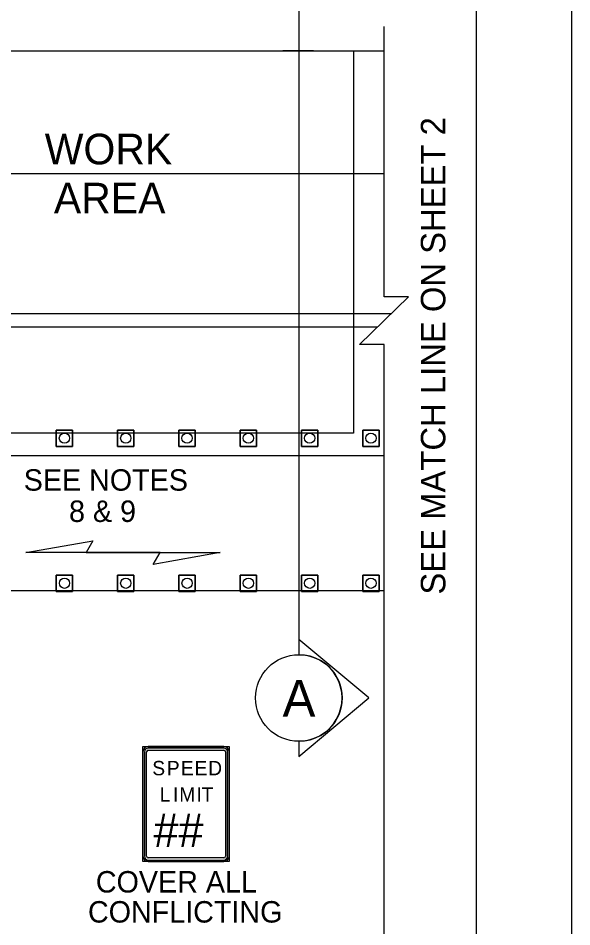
# Model space of a CAD drawing. Extents: x 99979.8 to 100075.7, y 99995 to 100010.7.
# Drawn here: x 100014.256 to 100016.062, y 100005.082 to 100008.046 of the extents above; entities that cross this region are included whole.
import ezdxf

# ---------------------------------------------------------------- set-up
doc = ezdxf.new("R2010")
doc.units = 0
for name, color, linetype in [('RD_ED_ShoulderPavedEdge', 7, 'Continuous'), ('RD_MK_LineEdgeWhite', 7, 'Continuous'), ('RD_MK_LineNoPass', 7, 'Continuous'), ('SH_GI_PlotLimits', 7, 'Continuous'), ('SH_GI_SheetBorder', 7, 'Continuous'), ('SH_TI_WZSectionCut', 7, 'Continuous'), ('TR_SN_ConstructionSigns', 7, 'Continuous'), ('TR_WZ_TrafficCone', 7, 'Continuous'), ('TR_WZ_WorkAreaLabel', 7, 'Continuous'), ('TR_WZ_WorkZoneDetails', 7, 'Continuous'), ('TR_WZ_WorkZoneTextCurrent', 7, 'Continuous')]:
    doc.layers.add(name, color=color, linetype=linetype)

msp = doc.modelspace()

# ---------------------------------------------------------------- linework, layer by layer
at = {"layer": 'RD_ED_ShoulderPavedEdge'}
for p, q in [((100000.1076, 100007.9393), (100015.45, 100007.9393)), ((100015.2197, 100007.9393), (100015.1196, 100007.9393)), ((100000.1076, 100006.1793), (100015.45, 100006.1793))]:
    msp.add_line(p, q, dxfattribs=at)
at = {"layer": 'RD_MK_LineEdgeWhite'}
for p, q in [((100013.0613, 100007.5393), (100015.45, 100007.5393)), ((100013.0469, 100006.6193), (100015.45, 100006.6193))]:
    msp.add_line(p, q, dxfattribs=at)
at = {"layer": 'RD_MK_LineNoPass'}
for p, q in [((100013.0613, 100007.0826), (100015.4741, 100007.0826)), ((100013.0613, 100007.0393), (100015.4293, 100007.0393))]:
    msp.add_line(p, q, dxfattribs=at)
at = {"layer": 'SH_GI_PlotLimits'}
msp.add_lwpolyline([(99999.0625, 99999.6875), (100016.0625, 99999.6875), (100016.0625, 100010.6875), (99999.0625, 100010.6875)], close=True, dxfattribs=at)
at = {"layer": 'SH_GI_SheetBorder'}
msp.add_line((100015.75, 100010.375), (100015.75, 100000), dxfattribs=at)
at = {"layer": 'SH_TI_WZSectionCut'}
for p, q in [((100015.1718, 100008.0993), (100015.1718, 100006.0193)), ((100015.1718, 100006.0193), (100015.1718, 100005.9694)), ((100015.4, 100005.8282), (100015.1718, 100006.0193)), ((100015.1718, 100005.637), (100015.4, 100005.8282)), ((100015.1718, 100005.687), (100015.1718, 100005.637))]:
    msp.add_line(p, q, dxfattribs=at)
msp.add_circle((100015.1718, 100005.8282), 0.1412, dxfattribs=at)
msp.add_arc((100015.1718, 100005.8282), 0.1412, 269.9978, 90.0022, dxfattribs=at)
at = {"layer": 'TR_SN_ConstructionSigns'}
for p, q in [((100014.6809, 100005.6698), (100014.927, 100005.6698)), ((100014.927, 100005.6698), (100014.6809, 100005.6698)), ((100014.6633, 100005.3123), (100014.6633, 100005.6522)), ((100014.6633, 100005.6522), (100014.6633, 100005.3123)), ((100014.6682, 100005.6522), (100014.6682, 100005.3123)), ((100014.6751, 100005.3123), (100014.6751, 100005.6522)), ((100014.927, 100005.6649), (100014.6809, 100005.6649)), ((100014.6809, 100005.658), (100014.927, 100005.658)), ((100014.9329, 100005.6522), (100014.9329, 100005.3123)), ((100014.9397, 100005.3123), (100014.9397, 100005.6522)), ((100014.9446, 100005.6522), (100014.9446, 100005.3123)), ((100014.9446, 100005.3123), (100014.9446, 100005.6522)), ((100014.927, 100005.3065), (100014.6809, 100005.3065)), ((100014.6809, 100005.2996), (100014.927, 100005.2996)), ((100014.927, 100005.2948), (100014.6809, 100005.2948)), ((100014.6809, 100005.2948), (100014.927, 100005.2948))]:
    msp.add_line(p, q, dxfattribs=at)
msp.add_lwpolyline([(100014.6633, 100005.6698), (100014.9446, 100005.6698), (100014.9446, 100005.2948), (100014.6633, 100005.2948)], close=True, dxfattribs=at)
for centre, radius, start, end in [((100014.6809, 100005.6522), 0.0176, 90, 180), ((100014.6809, 100005.6522), 0.0176, 90, 180), ((100014.927, 100005.6522), 0.0176, 0, 90), ((100014.927, 100005.6522), 0.0176, 0, 90), ((100014.6809, 100005.6522), 0.0127, 90, 180), ((100014.6809, 100005.6522), 0.00586, 90, 180), ((100014.927, 100005.6522), 0.0127, 0, 90), ((100014.927, 100005.6522), 0.00586, 360, 90), ((100014.6809, 100005.3123), 0.0176, 180, 270), ((100014.6809, 100005.3123), 0.0176, 180, 270), ((100014.6809, 100005.3123), 0.0127, 180, 270), ((100014.6809, 100005.3123), 0.00586, 180, 270), ((100014.927, 100005.3123), 0.0176, 270, 0), ((100014.927, 100005.3123), 0.0127, 270, 360), ((100014.927, 100005.3123), 0.00586, 270, 0), ((100014.927, 100005.3123), 0.0176, 270, 0)]:
    msp.add_arc(centre, radius, start, end, dxfattribs=at)
at = {"layer": 'TR_WZ_TrafficCone'}
for points in [[(100014.4339, 100006.7026), (100014.3805, 100006.7026), (100014.3805, 100006.6493), (100014.4339, 100006.6493), (100014.4339, 100006.7026)], [(100014.4339, 100006.6493), (100014.3805, 100006.6493), (100014.3805, 100006.7026), (100014.4339, 100006.7026), (100014.4339, 100006.6493)], [(100014.6339, 100006.7026), (100014.5805, 100006.7026), (100014.5805, 100006.6493), (100014.6339, 100006.6493), (100014.6339, 100006.7026)], [(100014.6339, 100006.6493), (100014.5805, 100006.6493), (100014.5805, 100006.7026), (100014.6339, 100006.7026), (100014.6339, 100006.6493)], [(100014.8339, 100006.7026), (100014.7805, 100006.7026), (100014.7805, 100006.6493), (100014.8339, 100006.6493), (100014.8339, 100006.7026)], [(100014.8339, 100006.6493), (100014.7805, 100006.6493), (100014.7805, 100006.7026), (100014.8339, 100006.7026), (100014.8339, 100006.6493)], [(100015.0339, 100006.7026), (100014.9805, 100006.7026), (100014.9805, 100006.6493), (100015.0339, 100006.6493), (100015.0339, 100006.7026)], [(100015.0339, 100006.6493), (100014.9805, 100006.6493), (100014.9805, 100006.7026), (100015.0339, 100006.7026), (100015.0339, 100006.6493)], [(100015.2339, 100006.7026), (100015.1805, 100006.7026), (100015.1805, 100006.6493), (100015.2339, 100006.6493), (100015.2339, 100006.7026)], [(100015.2339, 100006.6493), (100015.1805, 100006.6493), (100015.1805, 100006.7026), (100015.2339, 100006.7026), (100015.2339, 100006.6493)], [(100015.4339, 100006.7026), (100015.3805, 100006.7026), (100015.3805, 100006.6493), (100015.4339, 100006.6493), (100015.4339, 100006.7026)], [(100015.4339, 100006.6493), (100015.3805, 100006.6493), (100015.3805, 100006.7026), (100015.4339, 100006.7026), (100015.4339, 100006.6493)], [(100014.3806, 100006.2293), (100014.434, 100006.2293), (100014.434, 100006.176), (100014.3806, 100006.176), (100014.3806, 100006.2293)], [(100014.3806, 100006.176), (100014.434, 100006.176), (100014.434, 100006.2293), (100014.3806, 100006.2293), (100014.3806, 100006.176)], [(100014.5806, 100006.2293), (100014.634, 100006.2293), (100014.634, 100006.176), (100014.5806, 100006.176), (100014.5806, 100006.2293)], [(100014.5806, 100006.176), (100014.634, 100006.176), (100014.634, 100006.2293), (100014.5806, 100006.2293), (100014.5806, 100006.176)], [(100014.7806, 100006.2293), (100014.834, 100006.2293), (100014.834, 100006.176), (100014.7806, 100006.176), (100014.7806, 100006.2293)], [(100014.7806, 100006.176), (100014.834, 100006.176), (100014.834, 100006.2293), (100014.7806, 100006.2293), (100014.7806, 100006.176)], [(100014.9806, 100006.2293), (100015.034, 100006.2293), (100015.034, 100006.176), (100014.9806, 100006.176), (100014.9806, 100006.2293)], [(100014.9806, 100006.176), (100015.034, 100006.176), (100015.034, 100006.2293), (100014.9806, 100006.2293), (100014.9806, 100006.176)], [(100015.1806, 100006.2293), (100015.234, 100006.2293), (100015.234, 100006.176), (100015.1806, 100006.176), (100015.1806, 100006.2293)], [(100015.1806, 100006.176), (100015.234, 100006.176), (100015.234, 100006.2293), (100015.1806, 100006.2293), (100015.1806, 100006.176)], [(100015.3806, 100006.2293), (100015.434, 100006.2293), (100015.434, 100006.176), (100015.3806, 100006.176), (100015.3806, 100006.2293)], [(100015.3806, 100006.176), (100015.434, 100006.176), (100015.434, 100006.2293), (100015.3806, 100006.2293), (100015.3806, 100006.176)]]:
    msp.add_lwpolyline(points, dxfattribs=at)
for centre in [(100014.4072, 100006.676), (100014.6072, 100006.676), (100014.8072, 100006.676), (100015.0072, 100006.676), (100015.2072, 100006.676), (100015.4072, 100006.676), (100014.4073, 100006.2026), (100014.6073, 100006.2026), (100014.8073, 100006.2026), (100015.0073, 100006.2026), (100015.2073, 100006.2026), (100015.4073, 100006.2026)]:
    msp.add_circle(centre, 0.0167, dxfattribs=at)
at = {"layer": 'TR_WZ_WorkZoneDetails'}
for p, q in [((100014.7191, 100006.3026), (100014.478, 100006.3026)), ((100014.478, 100006.3026), (100014.7191, 100006.3026))]:
    msp.add_line(p, q, dxfattribs=at)
msp.add_lwpolyline([(100015.45, 100004.4092), (100015.45, 100006.9819), (100015.3699, 100006.9819), (100015.53, 100007.1367), (100015.45, 100007.1367), (100015.45, 100008.0193)], dxfattribs=at)
for points in [[(100015.35, 100006.6926), (100014.0546, 100006.6926), (100013.0613, 100006.6926), (100013.0613, 100007.0831), (100013.0613, 100007.0831), (100013.0613, 100007.0831), (100013.0613, 100007.3825), (100013.0613, 100007.3825), (100013.0613, 100007.3825), (100013.0613, 100007.6728), (100013.0613, 100007.9393), (100013.513, 100007.9393), (100014.3391, 100007.9393), (100015.35, 100007.9393), (100015.35, 100007.5174)], [(100014.2814, 100006.3026), (100014.5003, 100006.3412), (100014.478, 100006.3026)], [(100014.9156, 100006.3026), (100014.6968, 100006.264), (100014.7191, 100006.3026)]]:
    msp.add_lwpolyline(points, close=True, dxfattribs=at)

# ---------------------------------------------------------------- texts
at = {"layer": 'SH_TI_WZSectionCut'}
msp.add_text('A', height=0.12, rotation=0.01, dxfattribs=at).set_placement((100015.1189, 100005.7673))
at = {"layer": 'TR_SN_ConstructionSigns'}
for s, height, p in [('S', 0.0469, (100014.6938, 100005.576)), ('P', 0.0469, (100014.7412, 100005.576)), ('E', 0.0469, (100014.7871, 100005.576)), ('E', 0.0469, (100014.8316, 100005.576)), ('D', 0.0469, (100014.8762, 100005.576)), ('L', 0.0469, (100014.7182, 100005.4901)), ('I', 0.0469, (100014.7613, 100005.4901)), ('M', 0.0469, (100014.7819, 100005.4901)), ('I', 0.0469, (100014.8382, 100005.4901)), ('T', 0.0469, (100014.8546, 100005.4901)), ('##', 0.10937, (100014.6979, 100005.3416)), ('COVER ALL', 0.07, (100014.5097, 100005.1935)), ('CONFLICTING', 0.07, (100014.484, 100005.0955))]:
    msp.add_text(s, height=height, dxfattribs=at).set_placement(p)
at = {"layer": 'TR_WZ_WorkAreaLabel'}
for s, p in [('WORK', (100014.343, 100007.5693)), ('AREA', (100014.3727, 100007.4093))]:
    msp.add_text(s, height=0.1, dxfattribs=at).set_placement(p)
at = {"layer": 'TR_WZ_WorkZoneTextCurrent'}
msp.add_text('SEE MATCH LINE ON SHEET 2', height=0.08, rotation=90, dxfattribs=at).set_placement((100015.65, 100006.1658))
for s, p in [('SEE NOTES', (100014.2744, 100006.5046)), ('8 & 9', (100014.4222, 100006.4026))]:
    msp.add_text(s, height=0.07, dxfattribs=at).set_placement(p)

doc.saveas('drawing.dxf')
